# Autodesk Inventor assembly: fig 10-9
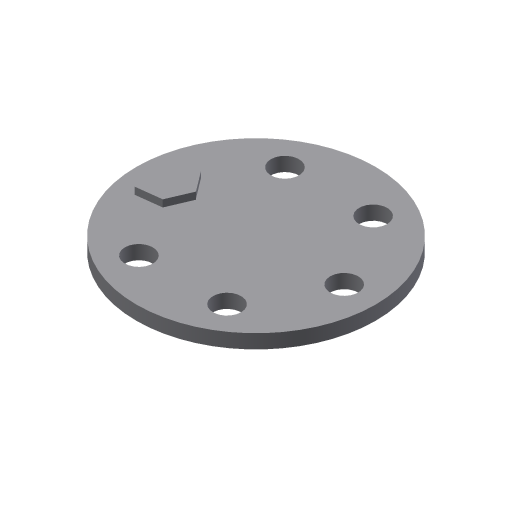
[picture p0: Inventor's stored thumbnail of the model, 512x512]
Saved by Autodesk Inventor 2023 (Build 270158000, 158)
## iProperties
Created: 2008-05
Part Number: fig 10-9
Document SubType Name: Assembly
Designer: CADCIM
Author: CADCIM
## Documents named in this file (3)
- D:\PROJECTS\Project 2022\Autodesk Inventor For Professional 2023\RESOURCES INVENTOR 2023\RESOURCES INVENTOR 2023\Inventor_2023_Part\Inventor_2023_Part\c10_Inv_2023_prt\fig 10-9.iam
- D:\PROJECTS\Project 2022\Autodesk Inventor For Professional 2023\RESOURCES INVENTOR 2023\RESOURCES INVENTOR 2023\Inventor_2023_Part\Inventor_2023_Part\c10_Inv_2023_prt\Part4.ipt
- D:\PROJECTS\Project 2022\Autodesk Inventor For Professional 2023\RESOURCES INVENTOR 2023\RESOURCES INVENTOR 2023\Inventor_2023_Part\Inventor_2023_Part\c10_Inv_2023_prt\Part5.ipt
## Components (2 placed, 2 different names)
1. Part4:1
2. Part5:1
